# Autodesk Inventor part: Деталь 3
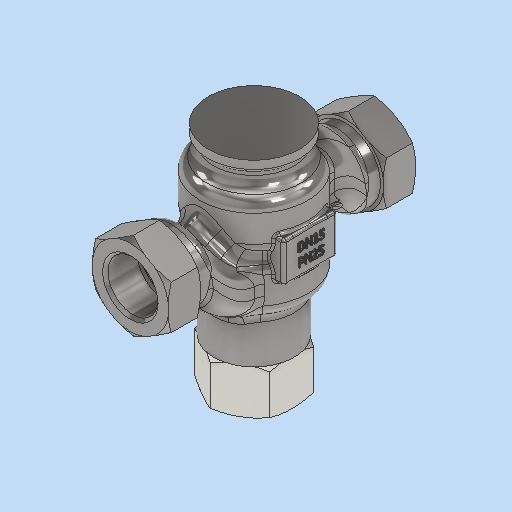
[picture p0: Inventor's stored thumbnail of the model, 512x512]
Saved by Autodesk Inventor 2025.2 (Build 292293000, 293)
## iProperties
Created: 2026-04
Part Number: Деталь 3
Material: Типовые
Document SubType Name: Modeling
Designer: igorr
Density: 1 g/cm^3
Appearance: По умолчанию
Author: igorr
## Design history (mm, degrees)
node "РабПлоскость1"
sketch "Эскиз3"
  geometry: L1 (-14.06, 8.118)-(0, 16.235); L2 (0, 16.235)-(14.06, 8.118); L3 (14.06, 8.118)-(14.06, -8.118); L4 (14.06, -8.118)-(0, -16.235); L5 (0, -16.235)-(-14.06, -8.118); L6 (-14.06, -8.118)-(-14.06, 8.118); C1 r 12.06 at (0, 0); C2 r 9.315 at (0, 0); 3 further points
  constraints: 12 end point, 3 coincident, 2 centre point, 1 horizontal alignment, 1 midpoint, 15 other
  dimensions: "d9" = 24.12 diameter of C1; "d10" = 2 dimension on C1; "d20" = 18.63 diameter of C2
extrude "Выдавливание3" new body sketch "Эскиз3" distance "d11" = 12; taper "d12" = 0 deg
sketch "Эскиз4"
  geometry: C1 r 12.06 at (0, 0) reference; C2 r 13.06 at (0, 0); C3 r 7.5 at (0, 0); 1 further point
  constraints: 2 centre point, 1 coincident
  dimensions: "d13" = 1 radial gap between concentric circles of C1 C2; "d14" = 15 diameter of C3
extrude "Выдавливание4" join sketch "Эскиз4" distance "d15" = 5; taper "d16" = 0 deg
sketch "Эскиз5"
  geometry: L1 (-12.06, -46)-(12.06, -46) reference; L2 (0, -46)-(0, -54.797); L3 (8.118, -46)-(16.235, -46) reference; L4 (16.235, -46)-(14.235, -46); L5 (14.235, -46)-(20.085, -42.622); L6 (20.085, -42.622)-(20.085, -46); L7 (20.085, -46)-(14.235, -46); L8 (16.235, -46)-(16.235, -34) reference; L9 (16.235, -40)-(17.87, -40); L10 (14.235, -34)-(20.085, -37.378); L11 (20.085, -37.378)-(20.085, -34); L12 (20.085, -34)-(14.235, -34); 2 further points
  constraints: 18 end point, 3 symmetric about line, 2 midpoint, 2 point on line, 1 collinear, 1 horizontal, 1 perpendicular, 1 vertical
  dimensions: "d17" = 2 distance of L3.end L4.end; "d18" = 30 deg angle of L4 L5
revolve "Вращение1" sketch "Эскиз5" stored, may be unused: angle "d19" = 90 deg
node "РабПлоскость2"
node "РабПлоскость4"
sketch "Эскиз13"
  geometry: L1 (7, 20)-(-7, 20); L2 (-15, 12)-(-15, 8); L3 (-7, 0)-(7, 0); L4 (15, 8)-(15, 12); L5 (15, 20)-(-15, 0); L6 (-15, 20)-(15, 0); A1 r 8 centre (7, 12) between (15, 12) and (7, 20); A2 r 8 centre (-7, 12) between (-7, 20) and (-15, 12); A3 r 8 centre (-7, 8) between (-15, 8) and (-7, 0); A4 r 8 centre (7, 8) between (7, 0) and (15, 8); 2 further points
  constraints: 12 end point, 8 point on circle, 8 point on line, 8 tangent, 4 centre point, 3 equal radius, 3 midpoint, 2 parallel, 1 horizontal, 1 perpendicular
  dimensions: "d60" = 30 distance of L5.start L6.start; "d61" = 20 distance of L5.end L6.start; "d62" = 8 radius of A1
feature "Лофт3" sketch "Эскиз13" dims "d63" = 0, "d64" = 90 deg, "d65" = 10, "d66" = 90 deg
  node "Ребра5"
fillet "Сопряжение11" dims "d73" = 4
mirror "Зеркальное отражение6"
mirror "Зеркальное отражение7"
sketch "Эскиз15"
  geometry: C1 r 20 at (0, 0); 1 further point
  constraints: 1 centre point, 1 coincident
  dimensions: "d74" = 40 diameter of C1
extrude "Выдавливание9" join sketch "Эскиз15" distance "d75" = 20; taper "d76" = 0 deg
fillet "Сопряжение12" dims "d77" = 5
sketch "Эскиз16"
  geometry: C1 r 20 at (0, 0); 1 further point
  constraints: 1 centre point, 1 coincident
  dimensions: "d78" = 40 diameter of C1
extrude "Выдавливание10" join sketch "Эскиз16" distance "d79" = 20; taper "d80" = 0 deg
fillet "Сопряжение13" dims "d81" = 5
feature "Комбинировать1"
  node "Твердое тело3"
fillet "Сопряжение14" dims "d82" = 4
sketch "Эскиз17"
  geometry: L1 (-7.5, 10)-(7.5, 10); L2 (7.5, 10)-(7.5, -10); L3 (7.5, -10)-(-7.5, -10); L4 (-7.5, -10)-(-7.5, 10); L5 (-7.5, 10)-(7.5, -10); L6 (7.5, 10)-(-7.5, -10); 1 further point
  constraints: 12 end point, 2 midpoint, 2 parallel, 1 horizontal, 1 perpendicular
  dimensions: "d83" = 15 distance of L1.start L1.end; "d84" = 20 distance of L1.end L2.end
extrude "Выдавливание11" join sketch "Эскиз17" distance "d85" = 21; taper "d86" = 0 deg
fillet "Сопряжение15" dims "d87" = 1
sketch "Эскиз18"
  geometry: C1 r 15 at (0, 0); 1 further point
  constraints: 1 centre point, 1 coincident
  dimensions: "d88" = 30 diameter of C1
extrude "Выдавливание12" join sketch "Эскиз18" distance "d89" = 18; taper "d90" = 0 deg
sketch "Эскиз19"
  geometry: L1 (14.06, -8.118)-(0, -16.235); L2 (0, -16.235)-(-14.06, -8.118); L3 (-14.06, -8.118)-(-14.06, 8.118); L4 (-14.06, 8.118)-(0, 16.235); L5 (0, 16.235)-(14.06, 8.118); L6 (14.06, 8.118)-(14.06, -8.118); C1 r 12.06 at (0, 0); C2 r 9.315 at (0, 0); 3 further points
  constraints: 12 end point, 3 coincident, 2 centre point, 1 horizontal alignment, 1 midpoint, 15 other
  dimensions: "d91" = 24.12 diameter of C1; "d92" = 2 dimension on C1; "d93" = 18.63 diameter of C2
extrude "Выдавливание13" join sketch "Эскиз19" distance "d94" = 17; taper "d95" = 0 deg
sketch "Эскиз20"
  geometry: C1 r 7.5 at (0, 0); 1 further point
  constraints: 1 centre point, 1 coincident
  dimensions: "d96" = 15 diameter of C1
extrude "Выдавливание14" cut sketch "Эскиз20" distance "d97" = 17; taper "d98" = 0 deg
sketch "Эскиз21"
  geometry: L1 (-55, -16.235)-(-55, -8.118) reference; L2 (-55, -16.235)-(-55, -14.235); L3 (-55, -14.235)-(-53.845, -16.235); L4 (-38, -16.235)-(-55, -16.235) reference; L5 (-53.845, -16.235)-(-55, -16.235); L6 (-55, 8.118)-(-55, -8.118) reference; L7 (-55, 0)-(-60.309, 0); L8 (-46.5, -16.235)-(-46.5, -19.962); L9 (-38, -16.235)-(-38, -14.235); L10 (-38, -14.235)-(-39.155, -16.235); L11 (-39.155, -16.235)-(-38, -16.235); 2 further points
  constraints: 16 end point, 2 midpoint, 2 point on line, 2 symmetric about line, 1 collinear, 1 horizontal, 1 vertical
  dimensions: "d99" = 2 distance of L1.start L2.end; "d100" = 30 deg angle of L2 L3
revolve "Вращение2" sketch "Эскиз21" stored, may be unused: angle "d101" = 360 deg
sketch "Эскиз22"
  geometry: C1 r 7.5 at (0, 0) reference; C2 r 15 at (0, 0); 1 further point
  constraints: 1 centre point, 1 coincident
  dimensions: "d103" = 30 diameter of C2
extrude "Выдавливание15" join sketch "Эскиз22" distance "d104" = 10; taper "d105" = 0 deg
fillet "Сопряжение16" dims "d102" = 5
sketch "Эскиз23"
  geometry: L1 (-6.1, 4.242)-(6.161, 4.242); L2 (6.161, 4.242)-(6.161, 1.13); L3 (6.161, 1.13)-(-6.1, 1.13); L4 (-6.1, 1.13)-(-6.1, 4.242); 1 further point
  constraints: 2 other
feature "Рельеф1" sketch "Эскиз23" dims "d17" = 2, "d18" = 30 deg, "d106" = 0.5, "d107" = 0
chamfer "Фаска1" distance "d108" = 1; stored, may be unused: second distance "d109" = 2, angle "d110" = 45 deg
sketch "Эскиз24"
  geometry: C1 r 17 at (0, 0); 1 further point
  constraints: 1 centre point, 1 coincident
  dimensions: "d111" = 34 diameter of C1
extrude "Выдавливание16" join sketch "Эскиз24" distance "d112" = 4; taper "d113" = 0 deg
fillet "Сопряжение17" dims "d114" = 1
feature "ʠ耀ʢ耀ʤ耀ʦ耀ʨ耀ʪ耀ʬ耀ʮ耀" dims "d8" = -46, "d9" = 24.12, "d10" = 2, "d11" = 12, "d12" = 0, "d13" = 1, "d14" = 15, "d15" = 5, "d16" = 0, "d17" = 2, "d18" = 30 deg, "d19" = 90 deg, "d20" = 18.63, "d27" = 15, "d54" = 16, "d60" = 30, "d61" = 20, "d62" = 8, "d63" = 0, "d64" = 90 deg, "d65" = 10, "d66" = 90 deg, "d73" = 4, "d74" = 40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
node "Твердое тело2"
feature "Шаблон Твердое тело2:1"
